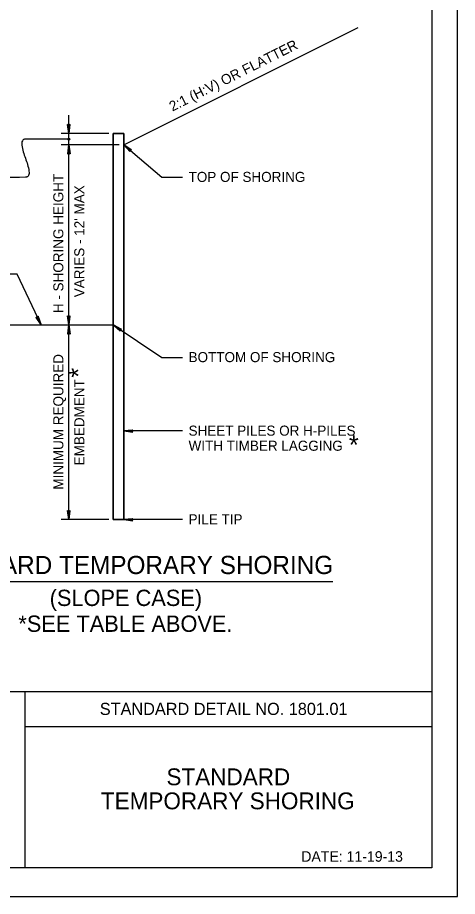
# Model space of a CAD drawing. Extents: x 1252282 to 1252638, y 733735 to 733845.
# Drawn here: x 1252608.4 to 1252638, y 733734.5 to 733793.6 of the extents above; entities that cross this region are included whole.
import ezdxf

# ---------------------------------------------------------------- set-up
doc = ezdxf.new("R2010")
doc.units = 0
for name, color, linetype in [('Default', 7, 'Continuous'), ('Sheet Plot Border Outside CELL', 7, 'Continuous'), ('Sheet Typical CELL', 7, 'Continuous')]:
    doc.layers.add(name, color=color, linetype=linetype)

msp = doc.modelspace()

# ---------------------------------------------------------------- linework, layer by layer
at = {"layer": 'Default'}
for p, q in [((1252615.523, 733785.037), (1252631.294, 733792.923)), ((1252611.825, 733759.837), (1252611.825, 733787.04)), ((1252611.825, 733785.795), (1252611.742, 733786.408)), ((1252611.825, 733786.329), (1252611.742, 733786.408)), ((1252611.825, 733785.795), (1252611.754, 733786.397)), ((1252611.825, 733785.795), (1252611.908, 733786.408)), ((1252611.908, 733786.408), (1252611.825, 733786.329)), ((1252611.896, 733786.397), (1252611.825, 733785.795)), ((1252611.765, 733786.385), (1252611.825, 733785.795)), ((1252611.825, 733785.795), (1252611.777, 733786.374)), ((1252611.79, 733786.362), (1252611.825, 733785.795)), ((1252611.825, 733785.795), (1252611.801, 733786.352)), ((1252611.813, 733786.34), (1252611.825, 733785.795)), ((1252611.825, 733785.795), (1252611.884, 733786.385)), ((1252611.872, 733786.374), (1252611.825, 733785.795)), ((1252611.825, 733785.795), (1252611.86, 733786.362)), ((1252611.849, 733786.352), (1252611.825, 733785.795)), ((1252611.825, 733785.795), (1252611.837, 733786.34)), ((1252611.825, 733786.329), (1252611.825, 733785.795)), ((1252614.514, 733785.795), (1252611.319, 733785.795)), ((1252615.523, 733785.795), (1252614.816, 733785.795)), ((1252615.523, 733785.795), (1252614.816, 733785.795)), ((1252614.816, 733785.795), (1252614.816, 733772.922)), ((1252614.816, 733772.922), (1252614.816, 733785.795)), ((1252615.523, 733772.922), (1252615.523, 733785.795)), ((1252615.523, 733772.922), (1252615.523, 733785.795)), ((1252615.22, 733785.037), (1252611.319, 733785.037)), ((1252611.825, 733785.037), (1252611.741, 733784.425)), ((1252611.753, 733784.436), (1252611.825, 733785.037)), ((1252611.825, 733785.037), (1252611.765, 733784.448)), ((1252611.777, 733784.459), (1252611.825, 733785.037)), ((1252611.825, 733785.037), (1252611.789, 733784.471)), ((1252611.8, 733784.481), (1252611.825, 733785.037)), ((1252611.825, 733785.037), (1252611.812, 733784.493)), ((1252611.825, 733785.037), (1252611.907, 733784.425)), ((1252611.825, 733784.504), (1252611.825, 733785.037)), ((1252611.836, 733784.493), (1252611.825, 733785.037)), ((1252611.825, 733785.037), (1252611.848, 733784.481)), ((1252611.859, 733784.471), (1252611.825, 733785.037)), ((1252611.825, 733785.037), (1252611.872, 733784.459)), ((1252611.884, 733784.448), (1252611.825, 733785.037)), ((1252611.825, 733785.037), (1252611.895, 733784.436)), ((1252615.523, 733785.037), (1252618.074, 733782.856)), ((1252615.523, 733785.037), (1252616.042, 733784.702)), ((1252615.523, 733785.037), (1252615.935, 733784.576)), ((1252615.934, 733784.593), (1252615.523, 733785.037)), ((1252615.523, 733785.037), (1252615.933, 733784.609)), ((1252615.932, 733784.625), (1252615.523, 733785.037)), ((1252615.523, 733785.037), (1252615.931, 733784.643)), ((1252615.93, 733784.658), (1252615.523, 733785.037)), ((1252615.523, 733785.037), (1252615.929, 733784.674)), ((1252615.929, 733784.691), (1252615.523, 733785.037)), ((1252615.944, 733784.692), (1252615.523, 733785.037)), ((1252615.523, 733785.037), (1252615.961, 733784.694)), ((1252615.977, 733784.696), (1252615.523, 733785.037)), ((1252615.523, 733785.037), (1252615.994, 733784.698)), ((1252616.01, 733784.699), (1252615.523, 733785.037)), ((1252615.523, 733785.037), (1252616.026, 733784.7)), ((1252615.929, 733784.691), (1252616.042, 733784.702)), ((1252615.935, 733784.576), (1252615.929, 733784.691)), ((1252611.741, 733784.425), (1252611.825, 733784.504)), ((1252611.825, 733784.504), (1252611.907, 733784.425)), ((1252618.074, 733782.856), (1252619.483, 733782.856)), ((1252609.957, 733772.922), (1252609.621, 733773.44)), ((1252609.729, 733773.404), (1252609.621, 733773.44)), ((1252609.957, 733772.922), (1252609.637, 733773.435)), ((1252609.652, 733773.429), (1252609.957, 733772.922)), ((1252609.957, 733772.922), (1252609.667, 733773.424)), ((1252609.683, 733773.419), (1252609.957, 733772.922)), ((1252609.957, 733772.922), (1252609.699, 733773.415)), ((1252609.714, 733773.409), (1252609.957, 733772.922)), ((1252609.771, 733773.511), (1252609.729, 733773.404)), ((1252609.729, 733773.404), (1252609.957, 733772.922)), ((1252609.957, 733772.922), (1252609.736, 733773.419)), ((1252609.741, 733773.435), (1252609.957, 733772.922)), ((1252609.957, 733772.922), (1252609.747, 733773.449)), ((1252609.753, 733773.465), (1252609.957, 733772.922)), ((1252609.957, 733772.922), (1252609.759, 733773.48)), ((1252609.765, 733773.496), (1252609.957, 733772.922)), ((1252609.957, 733772.922), (1252609.771, 733773.511)), ((1252611.825, 733772.922), (1252611.742, 733773.534)), ((1252611.825, 733773.455), (1252611.742, 733773.534)), ((1252611.825, 733772.922), (1252611.754, 733773.523)), ((1252611.765, 733773.511), (1252611.825, 733772.922)), ((1252611.825, 733772.922), (1252611.777, 733773.5)), ((1252611.79, 733773.488), (1252611.825, 733772.922)), ((1252611.825, 733772.922), (1252611.801, 733773.478)), ((1252611.813, 733773.466), (1252611.825, 733772.922)), ((1252611.825, 733772.922), (1252611.908, 733773.534)), ((1252611.908, 733773.534), (1252611.825, 733773.455)), ((1252611.896, 733773.523), (1252611.825, 733772.922)), ((1252611.825, 733772.922), (1252611.884, 733773.511)), ((1252611.872, 733773.5), (1252611.825, 733772.922)), ((1252611.825, 733772.922), (1252611.86, 733773.488)), ((1252611.849, 733773.478), (1252611.825, 733772.922)), ((1252611.825, 733772.922), (1252611.837, 733773.466)), ((1252611.825, 733773.455), (1252611.825, 733772.922)), ((1252595.38, 733772.922), (1252614.816, 733772.922)), ((1252611.825, 733772.922), (1252611.741, 733772.309)), ((1252611.753, 733772.32), (1252611.825, 733772.922)), ((1252611.825, 733772.922), (1252611.765, 733772.332)), ((1252611.777, 733772.343), (1252611.825, 733772.922)), ((1252611.825, 733772.922), (1252611.789, 733772.355)), ((1252611.8, 733772.365), (1252611.825, 733772.922)), ((1252611.825, 733772.922), (1252611.812, 733772.377)), ((1252611.825, 733772.922), (1252611.907, 733772.309)), ((1252611.825, 733772.388), (1252611.825, 733772.922)), ((1252611.836, 733772.377), (1252611.825, 733772.922)), ((1252611.825, 733772.922), (1252611.848, 733772.365)), ((1252611.859, 733772.355), (1252611.825, 733772.922)), ((1252611.825, 733772.922), (1252611.872, 733772.343)), ((1252611.884, 733772.332), (1252611.825, 733772.922)), ((1252611.825, 733772.922), (1252611.895, 733772.32)), ((1252614.816, 733759.837), (1252614.816, 733772.922)), ((1252614.816, 733772.922), (1252614.816, 733759.837)), ((1252614.816, 733772.922), (1252618.074, 733770.74)), ((1252614.816, 733772.922), (1252615.371, 733772.649)), ((1252614.816, 733772.922), (1252615.279, 733772.512)), ((1252615.276, 733772.528), (1252614.816, 733772.922)), ((1252614.816, 733772.922), (1252615.273, 733772.544)), ((1252615.271, 733772.56), (1252614.816, 733772.922)), ((1252614.816, 733772.922), (1252615.268, 733772.577)), ((1252615.265, 733772.592), (1252614.816, 733772.922)), ((1252614.816, 733772.922), (1252615.262, 733772.609)), ((1252615.26, 733772.625), (1252614.816, 733772.922)), ((1252615.275, 733772.628), (1252614.816, 733772.922)), ((1252614.816, 733772.922), (1252615.292, 733772.631)), ((1252615.307, 733772.636), (1252614.816, 733772.922)), ((1252614.816, 733772.922), (1252615.324, 733772.639)), ((1252615.339, 733772.643), (1252614.816, 733772.922)), ((1252614.816, 733772.922), (1252615.355, 733772.646)), ((1252615.523, 733759.837), (1252615.523, 733772.922)), ((1252615.523, 733759.837), (1252615.523, 733772.922)), ((1252611.741, 733772.309), (1252611.825, 733772.388)), ((1252611.825, 733772.388), (1252611.907, 733772.309)), ((1252615.26, 733772.625), (1252615.371, 733772.649)), ((1252615.279, 733772.512), (1252615.26, 733772.625)), ((1252618.074, 733770.74), (1252619.483, 733770.74)), ((1252615.523, 733765.796), (1252616.135, 733765.878)), ((1252615.523, 733765.796), (1252616.124, 733765.866)), ((1252616.113, 733765.855), (1252615.523, 733765.796)), ((1252615.523, 733765.796), (1252616.102, 733765.843)), ((1252616.09, 733765.83), (1252615.523, 733765.796)), ((1252615.523, 733765.796), (1252616.079, 733765.819)), ((1252616.068, 733765.807), (1252615.523, 733765.796)), ((1252615.523, 733765.796), (1252616.135, 733765.712)), ((1252616.124, 733765.724), (1252615.523, 733765.796)), ((1252615.523, 733765.796), (1252616.113, 733765.736)), ((1252616.102, 733765.748), (1252615.523, 733765.796)), ((1252615.523, 733765.796), (1252616.09, 733765.76)), ((1252616.079, 733765.771), (1252615.523, 733765.796)), ((1252615.523, 733765.796), (1252616.068, 733765.783)), ((1252616.057, 733765.796), (1252615.523, 733765.796)), ((1252619.483, 733765.796), (1252615.523, 733765.796)), ((1252616.057, 733765.796), (1252616.135, 733765.878)), ((1252616.135, 733765.712), (1252616.057, 733765.796)), ((1252611.825, 733759.837), (1252611.742, 733760.449)), ((1252611.825, 733760.37), (1252611.742, 733760.449)), ((1252611.825, 733759.837), (1252611.754, 733760.438)), ((1252611.765, 733760.426), (1252611.825, 733759.837)), ((1252611.825, 733759.837), (1252611.777, 733760.415)), ((1252611.79, 733760.403), (1252611.825, 733759.837)), ((1252611.825, 733759.837), (1252611.908, 733760.449)), ((1252611.908, 733760.449), (1252611.825, 733760.37)), ((1252611.896, 733760.438), (1252611.825, 733759.837)), ((1252611.825, 733759.837), (1252611.884, 733760.426)), ((1252611.872, 733760.415), (1252611.825, 733759.837)), ((1252611.825, 733759.837), (1252611.86, 733760.403)), ((1252614.513, 733759.837), (1252611.319, 733759.837)), ((1252611.825, 733759.837), (1252611.801, 733760.393)), ((1252611.813, 733760.381), (1252611.825, 733759.837)), ((1252611.849, 733760.393), (1252611.825, 733759.837)), ((1252611.825, 733759.837), (1252611.837, 733760.381)), ((1252611.825, 733760.37), (1252611.825, 733759.837)), ((1252615.523, 733759.837), (1252614.816, 733759.837)), ((1252614.816, 733759.837), (1252615.523, 733759.837)), ((1252615.523, 733759.837), (1252616.135, 733759.919)), ((1252615.523, 733759.837), (1252616.124, 733759.907)), ((1252616.113, 733759.896), (1252615.523, 733759.837)), ((1252615.523, 733759.837), (1252616.102, 733759.884)), ((1252616.09, 733759.872), (1252615.523, 733759.837)), ((1252615.523, 733759.837), (1252616.079, 733759.86)), ((1252616.068, 733759.848), (1252615.523, 733759.837)), ((1252615.523, 733759.837), (1252616.135, 733759.754)), ((1252616.124, 733759.765), (1252615.523, 733759.837)), ((1252615.523, 733759.837), (1252616.113, 733759.777)), ((1252616.102, 733759.789), (1252615.523, 733759.837)), ((1252615.523, 733759.837), (1252616.09, 733759.802)), ((1252616.079, 733759.813), (1252615.523, 733759.837)), ((1252615.523, 733759.837), (1252616.068, 733759.825)), ((1252616.057, 733759.837), (1252615.523, 733759.837)), ((1252619.483, 733759.837), (1252615.523, 733759.837)), ((1252616.057, 733759.837), (1252616.135, 733759.919)), ((1252616.135, 733759.754), (1252616.057, 733759.837)), ((1252600.744, 733755.669), (1252629.595, 733755.669))]:
    msp.add_line(p, q, dxfattribs=at)
msp.add_lwpolyline([(1252614.816, 733785.795), (1252615.523, 733785.795), (1252615.523, 733759.837), (1252614.816, 733759.837)], close=True, dxfattribs=at)
msp.add_lwpolyline([(1252609.957, 733772.922), (1252608.347, 733776.329), (1252606.939, 733776.329)], dxfattribs=at)
msp.add_circle((1252611.825, 733785.416), 0.0713, dxfattribs=at)
msp.add_spline([(1252611.825, 733785.416), (1252608.905, 733785.416), (1252608.867, 733785.415), (1252608.833, 733785.409), (1252608.776, 733785.388), (1252608.698, 733785.306), (1252608.668, 733785.017), (1252608.905, 733784.137), (1252609.142, 733783.258), (1252609.112, 733782.968), (1252609.035, 733782.887), (1252608.977, 733782.865), (1252608.943, 733782.86), (1252608.905, 733782.858), (1252602.574, 733782.858)], degree=3, dxfattribs=at)
at = {"layer": 'Sheet Plot Border Outside CELL'}
msp.add_lwpolyline([(1252467.333, 733734.502), (1252637.975, 733734.502), (1252637.975, 733844.502), (1252467.333, 733844.502)], close=True, dxfattribs=at)
at = {"layer": 'Sheet Typical CELL'}
msp.add_line((1252608.893, 733745.929), (1252636.257, 733745.929), dxfattribs=at)
for points in [[(1252484.62, 733842.575), (1252636.257, 733842.575), (1252636.257, 733736.429), (1252484.62, 733736.429)], [(1252575.799, 733748.291), (1252636.257, 733748.291), (1252636.257, 733736.429), (1252575.799, 733736.429)], [(1252608.893, 733748.291), (1252636.257, 733748.291), (1252636.257, 733736.429), (1252608.893, 733736.429)]]:
    msp.add_lwpolyline(points, close=True, dxfattribs=at)

# ---------------------------------------------------------------- texts
at = {"layer": 'Default'}
for s, height, rotation, p in [('2:1 (H:V) OR FLATTER', 0.67788, 26.64141, (1252618.793, 733787.263)), ('H - SHORING HEIGHT', 0.67788, 90, (1252611.458, 733773.717)), ("VARIES - 12' MAX", 0.67788, 90, (1252612.869, 733774.788)), ('MINIMUM REQUIRED', 0.67788, 90, (1252611.458, 733761.853)), ('*', 1.271, 90, (1252613.102, 733769.379)), ('EMBEDMENT', 0.6779, 90, (1252612.869, 733763.486))]:
    msp.add_text(s, height=height, rotation=rotation, dxfattribs=at).set_placement(p)
for s, height, p in [('TOP OF SHORING', 0.67788, (1252619.884, 733782.54)), ('BOTTOM OF SHORING', 0.67788, (1252619.884, 733770.424)), ('SHEET PILES OR H-PILES', 0.67788, (1252619.884, 733765.48)), ('WITH TIMBER LAGGING', 0.67788, (1252619.884, 733764.466)), ('*', 1.271, (1252630.672, 733764.232)), ('PILE TIP', 0.6779, (1252619.884, 733759.521)), ('STANDARD TEMPORARY SHORING', 1.22323, (1252601.712, 733756.176)), ('(SLOPE CASE)', 1.09532, (1252610.537, 733754.029)), ('*SEE TABLE ABOVE.', 1.09532, (1252608.428, 733752.291)), ('STANDARD DETAIL NO. 1801.01', 0.81884, (1252613.908, 733746.701)), ('STANDARD', 1.1322, (1252618.395, 733741.978)), ('TEMPORARY SHORING', 1.13223, (1252613.984, 733740.361)), ('DATE: 11-19-13', 0.70764, (1252627.469, 733736.835))]:
    msp.add_text(s, height=height, dxfattribs=at).set_placement(p)

doc.saveas('drawing.dxf')
